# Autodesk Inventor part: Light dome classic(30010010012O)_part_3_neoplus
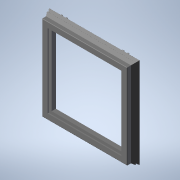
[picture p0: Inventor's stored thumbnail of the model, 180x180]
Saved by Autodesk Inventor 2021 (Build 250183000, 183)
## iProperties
Created: 2026-04
Part Number: Light dome classic(30010010012O)_part_3_neoplus
Material: Generic
Catalog Web Link: www.3dfindit.com
Description: Light dome classic_part_3_neoplus-
Vendor: KINGSPAN
Document SubType Name: Modeling
Designer: psAdmin
Manufacturer: KINGSPAN
Mass: 18628.4 g
Surface Area: 17069.3 cm^2
Volume: 18628.4 cm^3
Density: 1 g/cm^3
Appearance: PSOLRGB-255-255-255
Category: PARTsolutions
Company: KINGSPAN
Title: Light dome classic(30010010012O)_part_3_neoplus
Author: Cadenas PARTsolutions
PSOL_IDENT_0: {$CADENAS_DATA/23d-libs/kingspan_kla/light_dome_classic_neoplus/parts/part_3.prj},283 {VTYP=3D},{NB=
PSOL_IDENT_1: Light dome classic(30010010012O)_part_3_neoplus},{LINA=Light dome classic(30010010012O)_part_3_neopl
PSOL_IDENT_2: us},{NN=Light dome classic_part_3_neoplus},{DATE=20.03.2025 09:30:52},{GEOMDATE=01.07.2024 06:07:22}
PSOL_IDENT_3: ,{VERSION=},{LINEID=10},{WBVAR=LODLEVEL,L,W,DP,OP,OC},{WBNUMERIC=W}  {NB=Light dome classic(30010010
PSOL_IDENT_4: 012O)_part_3_neoplus},{LINA=Light dome classic(30010010012O)_part_3_neoplus},{KT=DUMMY},{IDNR=},{PN=
PSOL_IDENT_5: Light dome classic},{LODLEVEL=300},{L=100},{W=100},{DRIVE=1},{WX=100,150,200,250,300},{DP=1},{OP=2},
PSOL_IDENT_6: {OPX='1','manualy','2','Linear drive 300 mm stroke 24 V and 230 V','3','Linear drive 500 mm stroke 2
PSOL_IDENT_7: 4 V and 230 V','4','Linear drive 750 mm stroke 24 V and 230 V'},{LX=1000},{XWX=1000},{OC=O}
NB: Light dome classic(30010010012O)_part_3_neoplus
NN: Light dome classic_part_3_neoplus
NBSYN: $PN.($LODLEVEL.$L.$W.$DP.$OP.$OC.)_part_3_neoplus
LINA: Light dome classic(30010010012O)_part_3_neoplus
CATALOG: Light + Air
PN: Light dome classic
LODLEVEL: 300
L: 100
W: 100
DP: Natural ventilation
OP: Linear drive 300 mm stroke 24 V and 230 V
OC: Open
SUPPLIER: KINGSPAN
ARTICLENO: Light dome classic(30010010012O)_part_3_neoplus
BOMINFO: Light dome classic(30010010012O)_part_3_neoplus
CREATOR: CADENAS GmbH
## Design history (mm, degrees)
sketch "Sketch_1"
  geometry: L1 (-394, 25.446)-(-394, 71.946); L2 (-394, 71.946)-(-424, 71.946); L3 (-424, 71.946)-(-424, 103.596); L4 (-424, 103.596)-(-402, 103.596); L5 (-402, 103.596)-(-402, 106.946); L6 (-402, 106.946)-(-457, 106.946); L7 (-462, 101.946)-(-462, 45.447); L8 (-462, 45.447)-(-492.031, 1.954); L9 (-490.242, 0.252)-(-487.688, 2.21); L10 (-487.688, 2.21)-(-488.863, 3.022); L11 (-488.863, 3.022)-(-471, 28.893); L12 (-471, 28.893)-(-471, 17.946); L13 (-471, 17.946)-(-429.25, 17.946); L14 (-429.25, 17.946)-(-429.25, 21.946); L15 (-429.25, 21.946)-(-431.25, 21.946); L16 (-431.25, 21.946)-(-431.25, 19.946); L17 (-431.25, 19.946)-(-436.75, 19.946); L18 (-436.75, 19.946)-(-436.75, 23.946); L19 (-436.75, 23.946)-(-421.2, 23.946); L20 (-421.2, 23.946)-(-421.2, 25.446); L21 (-421.2, 25.446)-(-394, 25.446); A1 r 5 centre (-457, 101.946) between (-457, 106.946) and (-462, 101.946); A2 r 1.25 centre (-491.002, 1.244) between (-492.031, 1.954) and (-490.242, 0.252)
  constraints: 42 end point, 4 point on circle, 2 centre point
extrude "Extrusion1" join sketch "Sketch_1" stored distance "d0" = 2000; taper "d1" = 0 deg
sketch "Sketch_2"
  geometry: L1 (402, 106.946)-(402, 103.596); L2 (402, 103.596)-(424, 103.596); L3 (424, 103.596)-(424, 71.946); L4 (424, 71.946)-(394, 71.946); L5 (394, 71.946)-(394, 25.446); L6 (394, 25.446)-(421.2, 25.446); L7 (421.2, 25.446)-(421.2, 23.946); L8 (421.2, 23.946)-(436.75, 23.946); L9 (436.75, 23.946)-(436.75, 19.946); L10 (436.75, 19.946)-(431.25, 19.946); L11 (431.25, 19.946)-(431.25, 21.946); L12 (431.25, 21.946)-(429.25, 21.946); L13 (429.25, 21.946)-(429.25, 17.946); L14 (429.25, 17.946)-(471, 17.946); L15 (471, 17.946)-(471, 28.893); L16 (471, 28.893)-(488.863, 3.022); L17 (488.863, 3.022)-(487.688, 2.21); L18 (487.688, 2.21)-(490.242, 0.252); L19 (492.031, 1.954)-(462, 45.447); L20 (462, 45.447)-(462, 101.946); L21 (457, 106.946)-(402, 106.946); A1 r 1.25 centre (491.002, 1.244) between (490.242, 0.252) and (492.031, 1.954); A2 r 5 centre (457, 101.946) between (462, 101.946) and (457, 106.946)
  constraints: 42 end point, 4 point on circle, 2 centre point
extrude "Extrusion2" join sketch "Sketch_2" stored distance "d2" = 2000; taper "d3" = 0 deg
sketch "Sketch_3"
  geometry: L1 (492.031, 1.954)-(462, 45.447); L2 (462, 45.447)-(462, 101.946); L3 (457, 106.946)-(402, 106.946); L4 (402, 106.946)-(402, 103.596); L5 (402, 103.596)-(424, 103.596); L6 (424, 103.596)-(424, 71.946); L7 (424, 71.946)-(394, 71.946); L8 (394, 71.946)-(394, 25.446); L9 (394, 25.446)-(421.2, 25.446); L10 (421.2, 25.446)-(421.2, 23.946); L11 (421.2, 23.946)-(436.75, 23.946); L12 (436.75, 23.946)-(436.75, 19.946); L13 (436.75, 19.946)-(431.25, 19.946); L14 (431.25, 19.946)-(431.25, 21.946); L15 (431.25, 21.946)-(429.25, 21.946); L16 (429.25, 21.946)-(429.25, 17.946); L17 (429.25, 17.946)-(471, 17.946); L18 (471, 17.946)-(471, 28.893); L19 (471, 28.893)-(488.863, 3.022); L20 (488.863, 3.022)-(487.688, 2.21); L21 (487.688, 2.21)-(490.242, 0.252); A1 r 1.25 centre (491.002, 1.244) between (490.242, 0.252) and (492.031, 1.954); A2 r 5 centre (457, 101.946) between (462, 101.946) and (457, 106.946)
  constraints: 42 end point, 4 point on circle, 2 centre point
extrude "Extrusion3" join sketch "Sketch_3" stored distance "d4" = 2000; taper "d5" = 0 deg
sketch "Sketch_4"
  geometry: L1 (-402, 106.946)-(-457, 106.946); L2 (-462, 101.946)-(-462, 45.447); L3 (-462, 45.447)-(-492.031, 1.954); L4 (-490.242, 0.252)-(-487.688, 2.21); L5 (-487.688, 2.21)-(-488.863, 3.022); L6 (-488.863, 3.022)-(-471, 28.893); L7 (-471, 28.893)-(-471, 17.946); L8 (-471, 17.946)-(-429.25, 17.946); L9 (-429.25, 17.946)-(-429.25, 21.946); L10 (-429.25, 21.946)-(-431.25, 21.946); L11 (-431.25, 21.946)-(-431.25, 19.946); L12 (-431.25, 19.946)-(-436.75, 19.946); L13 (-436.75, 19.946)-(-436.75, 23.946); L14 (-436.75, 23.946)-(-421.2, 23.946); L15 (-421.2, 23.946)-(-421.2, 25.446); L16 (-421.2, 25.446)-(-394, 25.446); L17 (-394, 25.446)-(-394, 71.946); L18 (-394, 71.946)-(-424, 71.946); L19 (-424, 71.946)-(-424, 103.596); L20 (-424, 103.596)-(-402, 103.596); L21 (-402, 103.596)-(-402, 106.946); A1 r 5 centre (-457, 101.946) between (-457, 106.946) and (-462, 101.946); A2 r 1.25 centre (-491.002, 1.244) between (-492.031, 1.954) and (-490.242, 0.252)
  constraints: 42 end point, 4 point on circle, 2 centre point
extrude "Extrusion4" join sketch "Sketch_4" stored distance "d6" = 2000; taper "d7" = 0 deg
sketch "Sketch_5"
  geometry: L1 (-402, 156.946)-(-1000, 156.946); L2 (-1000, 156.946)-(-1000, -32.054); L3 (-1000, -32.054)-(-491.002, -32.054); L4 (-491.002, -32.054)-(-491.002, -0.006); L5 (-492.031, 1.954)-(-462, 45.447); L6 (-462, 45.447)-(-462, 101.946); L7 (-457, 106.946)-(-402, 106.946); L8 (-402, 106.946)-(-402, 156.946); A1 r 1.25 centre (-491.002, 1.244) between (-492.031, 1.954) and (-491.002, -0.006); A2 r 5 centre (-457, 101.946) between (-457, 106.946) and (-462, 101.946)
  constraints: 16 end point, 4 point on circle, 2 centre point
extrude "Extrusion5" cut sketch "Sketch_5" stored distance "d8" = 2000; taper "d9" = 0 deg
sketch "Sketch_6"
  geometry: L1 (1000, 156.946)-(402, 156.946); L2 (402, 156.946)-(402, 106.946); L3 (402, 106.946)-(457, 106.946); L4 (462, 101.946)-(462, 45.447); L5 (462, 45.447)-(492.031, 1.954); L6 (491.002, -0.006)-(491.002, -32.054); L7 (491.002, -32.054)-(1000, -32.054); L8 (1000, -32.054)-(1000, 156.946); A1 r 5 centre (457, 101.946) between (462, 101.946) and (457, 106.946); A2 r 1.25 centre (491.002, 1.244) between (491.002, -0.006) and (492.031, 1.954)
  constraints: 16 end point, 4 point on circle, 2 centre point
extrude "Extrusion6" cut sketch "Sketch_6" stored distance "d10" = 2000; taper "d11" = 0 deg
sketch "Sketch_7"
  geometry: L1 (1000, 156.946)-(402, 156.946); L2 (402, 156.946)-(402, 106.946); L3 (402, 106.946)-(457, 106.946); L4 (462, 101.946)-(462, 45.447); L5 (462, 45.447)-(492.031, 1.954); L6 (491.002, -0.006)-(491.002, -32.054); L7 (491.002, -32.054)-(1000, -32.054); L8 (1000, -32.054)-(1000, 156.946); A1 r 5 centre (457, 101.946) between (462, 101.946) and (457, 106.946); A2 r 1.25 centre (491.002, 1.244) between (491.002, -0.006) and (492.031, 1.954)
  constraints: 16 end point, 4 point on circle, 2 centre point
extrude "Extrusion7" cut sketch "Sketch_7" stored distance "d12" = 2000; taper "d13" = 0 deg
sketch "Sketch_8"
  geometry: L1 (-1000, 156.946)-(-1000, -32.054); L2 (-1000, -32.054)-(-491.002, -32.054); L3 (-491.002, -32.054)-(-491.002, -0.006); L4 (-492.031, 1.954)-(-462, 45.447); L5 (-462, 45.447)-(-462, 101.946); L6 (-457, 106.946)-(-402, 106.946); L7 (-402, 106.946)-(-402, 156.946); L8 (-402, 156.946)-(-1000, 156.946); A1 r 1.25 centre (-491.002, 1.244) between (-492.031, 1.954) and (-491.002, -0.006); A2 r 5 centre (-457, 101.946) between (-457, 106.946) and (-462, 101.946)
  constraints: 16 end point, 4 point on circle, 2 centre point
extrude "Extrusion8" cut sketch "Sketch_8" stored distance "d14" = 2000; taper "d15" = 0 deg
sketch "Sketch_9"
  geometry: L1 (-457, 34.19)-(-457, 71.429); L2 (-457, 71.429)-(-483.061, 32.792); L3 (-481.277, 31.71)-(-478.348, 34.19); L4 (-478.348, 34.19)-(-457, 34.19); A1 r 1.1 centre (-481.988, 32.55) between (-483.061, 32.792) and (-481.277, 31.71)
  constraints: 8 end point, 2 point on circle, 1 centre point
extrude "Extrusion9" join sketch "Sketch_9" stored distance "d16" = 2000; taper "d17" = 0 deg
sketch "Sketch_10"
  geometry: L1 (457, 71.429)-(457, 34.19); L2 (457, 34.19)-(478.348, 34.19); L3 (478.348, 34.19)-(481.277, 31.71); L4 (483.061, 32.792)-(457, 71.429); A1 r 1.1 centre (481.988, 32.55) between (481.277, 31.71) and (483.061, 32.792)
  constraints: 8 end point, 2 point on circle, 1 centre point
extrude "Extrusion10" join sketch "Sketch_10" stored distance "d18" = 2000; taper "d19" = 0 deg
sketch "Sketch_11"
  geometry: L1 (483.061, 32.792)-(457, 71.429); L2 (457, 71.429)-(457, 34.19); L3 (457, 34.19)-(478.348, 34.19); L4 (478.348, 34.19)-(481.277, 31.71); A1 r 1.1 centre (481.988, 32.55) between (481.277, 31.71) and (483.061, 32.792)
  constraints: 8 end point, 2 point on circle, 1 centre point
extrude "Extrusion11" join sketch "Sketch_11" stored distance "d20" = 2000; taper "d21" = 0 deg
sketch "Sketch_12"
  geometry: L1 (-457, 71.429)-(-483.061, 32.792); L2 (-481.277, 31.71)-(-478.348, 34.19); L3 (-478.348, 34.19)-(-457, 34.19); L4 (-457, 34.19)-(-457, 71.429); A1 r 1.1 centre (-481.988, 32.55) between (-483.061, 32.792) and (-481.277, 31.71)
  constraints: 8 end point, 2 point on circle, 1 centre point
extrude "Extrusion12" join sketch "Sketch_12" stored distance "d22" = 2000; taper "d23" = 0 deg
sketch "Sketch_13"
  geometry: L1 (-462, 74.016)-(-1481.988, 74.016); L2 (-1481.988, 74.016)-(-1481.988, 27.946); L3 (-1481.988, 27.946)-(-481.988, 27.946); L4 (-481.988, 27.946)-(-481.988, 31.45); L5 (-483.061, 32.792)-(-462, 64.016); L6 (-462, 64.016)-(-462, 74.016); A1 r 1.1 centre (-481.988, 32.55) between (-483.061, 32.792) and (-481.988, 31.45)
  constraints: 12 end point, 2 point on circle, 1 centre point
extrude "Extrusion13" cut sketch "Sketch_13" stored distance "d24" = 2000; taper "d25" = 0 deg
sketch "Sketch_14"
  geometry: L1 (1481.988, 27.946)-(1481.988, 74.016); L2 (1481.988, 74.016)-(462, 74.016); L3 (462, 74.016)-(462, 64.016); L4 (462, 64.016)-(483.061, 32.792); L5 (481.988, 31.45)-(481.988, 27.946); L6 (481.988, 27.946)-(1481.988, 27.946); A1 r 1.1 centre (481.988, 32.55) between (481.988, 31.45) and (483.061, 32.792)
  constraints: 12 end point, 2 point on circle, 1 centre point
extrude "Extrusion14" cut sketch "Sketch_14" stored distance "d26" = 2000; taper "d27" = 0 deg
sketch "Sketch_15"
  geometry: L1 (1481.988, 74.016)-(462, 74.016); L2 (462, 74.016)-(462, 64.016); L3 (462, 64.016)-(483.061, 32.792); L4 (481.988, 31.45)-(481.988, 27.946); L5 (481.988, 27.946)-(1481.988, 27.946); L6 (1481.988, 27.946)-(1481.988, 74.016); A1 r 1.1 centre (481.988, 32.55) between (481.988, 31.45) and (483.061, 32.792)
  constraints: 12 end point, 2 point on circle, 1 centre point
extrude "Extrusion15" cut sketch "Sketch_15" stored distance "d28" = 2000; taper "d29" = 0 deg
sketch "Sketch_16"
  geometry: L1 (-1481.988, 74.016)-(-1481.988, 27.946); L2 (-1481.988, 27.946)-(-481.988, 27.946); L3 (-481.988, 27.946)-(-481.988, 31.45); L4 (-483.061, 32.792)-(-462, 64.016); L5 (-462, 64.016)-(-462, 74.016); L6 (-462, 74.016)-(-1481.988, 74.016); A1 r 1.1 centre (-481.988, 32.55) between (-483.061, 32.792) and (-481.988, 31.45)
  constraints: 12 end point, 2 point on circle, 1 centre point
extrude "Extrusion16" cut sketch "Sketch_16" stored distance "d30" = 2000; taper "d31" = 0 deg
sketch "Sketch_17"
  geometry: L1 (-17.946, 471.802)-(-17.946, 449.665); L2 (-17.946, 449.665)-(-16.1, 445.05); L3 (-16.1, 445.05)-(-14.243, 445.793); L4 (-14.243, 445.793)-(-15.946, 450.05); L5 (-15.946, 450.05)-(-15.946, 470.837); L6 (-15.946, 470.837)-(7.12, 489.184); L7 (6.644, 487.499)-(4.764, 486.817); L8 (5.875, 490.749)-(-17.946, 471.802); A1 r 1.5 centre (8.054, 488.01) between (6.644, 487.499) and (7.12, 489.184); A2 r 3.5 centre (8.054, 488.01) between (4.764, 486.817) and (5.875, 490.749)
  constraints: 16 end point, 4 point on circle, 2 centre point
extrude "Extrusion17" join sketch "Sketch_17" distance "d32" = 70; taper "d33" = 0 deg
sketch "Sketch_18"
  geometry: L1 (-17.946, 471.802)-(-17.946, 449.665); L2 (-17.946, 449.665)-(-16.1, 445.05); L3 (-16.1, 445.05)-(-14.243, 445.793); L4 (-14.243, 445.793)-(-15.946, 450.05); L5 (-15.946, 450.05)-(-15.946, 470.837); L6 (-15.946, 470.837)-(7.12, 489.184); L7 (6.644, 487.499)-(4.764, 486.817); L8 (5.875, 490.749)-(-17.946, 471.802); A1 r 1.5 centre (8.054, 488.01) between (6.644, 487.499) and (7.12, 489.184); A2 r 3.5 centre (8.054, 488.01) between (4.764, 486.817) and (5.875, 490.749)
  constraints: 16 end point, 4 point on circle, 2 centre point
extrude "Extrusion18" join sketch "Sketch_18" distance "d34" = 70; taper "d35" = 0 deg
sketch "Sketch_19"
  geometry: L1 (-15.946, 511.757)-(16.193, 473.455); L2 (16.193, 473.455)-(31.514, 486.311); L3 (31.514, 486.311)-(-0.625, 524.613); L4 (-0.625, 524.613)-(-15.946, 511.757)
  constraints: 8 end point
extrude "Extrusion19" cut sketch "Sketch_19" stored distance "d36" = 38; taper "d37" = 0 deg
sketch "Sketch_20"
  geometry: L1 (-15.946, 511.757)-(16.193, 473.455); L2 (16.193, 473.455)-(31.514, 486.311); L3 (31.514, 486.311)-(-0.625, 524.613); L4 (-0.625, 524.613)-(-15.946, 511.757)
  constraints: 8 end point
extrude "Extrusion20" cut sketch "Sketch_20" stored distance "d38" = 38; taper "d39" = 0 deg
sketch "Sketch_21"
  geometry: L1 (-509.411, -2.354)-(-487.41, -2.354); L2 (-487.41, -2.354)-(-487.41, 8.646); L3 (-487.41, 8.646)-(-485.722, 11.091); L4 (-485.722, 11.091)-(-491.711, 19.644); A1 r 20 centre (-491.411, -0.354) between (-491.711, 19.644) and (-511.411, -0.354); A2 r 2 centre (-509.411, -0.354) between (-511.411, -0.354) and (-509.411, -2.354)
  constraints: 8 end point, 4 point on circle, 2 centre point
extrude "Extrusion21" join sketch "Sketch_21" stored distance "d40" = 41; taper "d41" = 0 deg
node "IP_3_XY"
node "IP_3_YZ"
node "IP_3_ZX"
node "IP_3_X"
node "IP_3_Y"
node "IP_3_Z"
node "IP_3_Center"
node "IP_for_part_11_1_XY"
node "IP_for_part_11_1_YZ"
node "IP_for_part_11_1_ZX"
node "IP_for_part_11_1_X"
node "IP_for_part_11_1_Y"
node "IP_for_part_11_1_Z"
node "IP_for_part_11_1_Center"
node "IP_for_part_4_XY"
node "IP_for_part_4_YZ"
node "IP_for_part_4_ZX"
node "IP_for_part_4_X"
node "IP_for_part_4_Y"
node "IP_for_part_4_Z"
node "IP_for_part_4_Center"
node "IP_for_part_5_XY"
node "IP_for_part_5_YZ"
node "IP_for_part_5_ZX"
node "IP_for_part_5_X"
node "IP_for_part_5_Y"
node "IP_for_part_5_Z"
node "IP_for_part_5_Center"
node "IP_for_part_6_XY"
node "IP_for_part_6_YZ"
node "IP_for_part_6_ZX"
node "IP_for_part_6_X"
node "IP_for_part_6_Y"
node "IP_for_part_6_Z"
node "IP_for_part_6_Center"
body "Solid1"
other parameters: "d42" = 0, "d43" = 0, "d44" = 0
